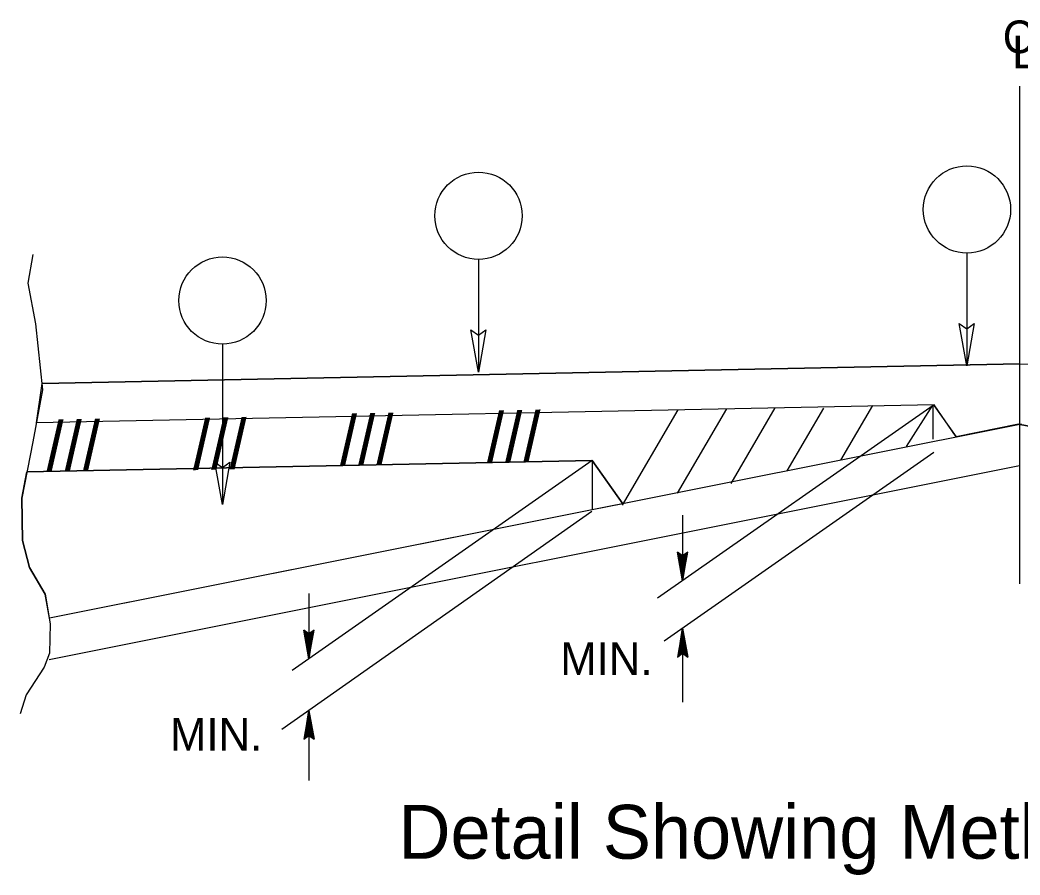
# Model space of a CAD drawing. Extents: x 1818040 to 1825768, y 638918 to 648046.
# Drawn here: x 1822960 to 1824344, y 641816 to 643000 of the extents above; entities that cross this region are included whole.
import ezdxf

# ---------------------------------------------------------------- set-up
doc = ezdxf.new("R2010")
doc.units = 0
for name, color, linetype in [('Typical Detail Wedge2 CELL', 7, 'Continuous'), ('Typical ID Circle CELL', 7, 'Continuous'), ('Typical Terminator CELL', 7, 'Continuous'), ('Typical Text Centerline CELL', 7, 'Continuous'), ('Typical Text General CELL', 7, 'Continuous')]:
    doc.layers.add(name, color=color, linetype=linetype)

msp = doc.modelspace()

# ---------------------------------------------------------------- linework, layer by layer
at = {"layer": 'Typical Detail Wedge2 CELL'}
for p, q in [((1824343.8, 642219), (1824343.8, 642908.2)), ((1824343.8, 642219), (1824343.8, 642689.7)), ((1824343.8, 642523.5), (1822991, 642496.5)), ((1822991, 642496.5), (1824343.8, 642523.5)), ((1824343.8, 642523.5), (1825696.6, 642496.5)), ((1822983.3, 642442.1), (1822991, 642496.5)), ((1824225.1, 642466.9), (1822983.3, 642442.1)), ((1824225.1, 642466.9), (1822983.3, 642442.1)), ((1823870.3, 642459.8), (1823793.4, 642328.1)), ((1824223.6, 642465.9), (1823842.4, 642199)), ((1823937.8, 642461.2), (1823869.8, 642344.4)), ((1824004.6, 642462.5), (1823943.6, 642357.8)), ((1824072, 642462.4), (1824021.3, 642375.7)), ((1824139.9, 642465.8), (1824095.7, 642390.2)), ((1824186.7, 642409.1), (1824223.4, 642466.4)), ((1824223.4, 642466.4), (1824223.4, 642419.3)), ((1824255.5, 642422.4), (1824225.1, 642466.9)), ((1824225.1, 642465.5), (1824255.5, 642422.4)), ((1824345.8, 642440.3), (1823001.2, 642171.3)), ((1824341.8, 642440.3), (1824255.5, 642422.4)), ((1824341.8, 642440.3), (1825686.5, 642171.3)), ((1824432.1, 642422.4), (1824341.8, 642440.3)), ((1823752, 642389.6), (1822970.1, 642374)), ((1822970.1, 642374), (1823752, 642389.6)), ((1823752, 642389.6), (1823336.8, 642098.9)), ((1823794.5, 642329.9), (1823752, 642389.6)), ((1823752, 642389.6), (1823752, 642321.4)), ((1823752, 642389.6), (1823794.4, 642330)), ((1824224.5, 642400.7), (1823851.5, 642139.5)), ((1824343.3, 642382.4), (1823000.7, 642113.9)), ((1823752, 642321.5), (1823615.8, 642294.3)), ((1823794.4, 642330), (1823752, 642321.5)), ((1823751.7, 642319.3), (1823322.5, 642017.3)), ((1823877.1, 642314), (1823877.1, 642223.3)), ((1823615.8, 642294.3), (1823001.2, 642171.3)), ((1823877.1, 642223.3), (1823870.1, 642263.1)), ((1823877.1, 642257.9), (1823870.1, 642263.1)), ((1823877.1, 642223.3), (1823871.1, 642262.3)), ((1823872.1, 642261.6), (1823877.1, 642223.3)), ((1823877.1, 642223.3), (1823873.1, 642260.9)), ((1823874.1, 642260.1), (1823877.1, 642223.3)), ((1823877.1, 642223.3), (1823875.1, 642259.4)), ((1823876.1, 642258.6), (1823877.1, 642223.3)), ((1823877.1, 642223.3), (1823884.2, 642263.1)), ((1823884.2, 642263.1), (1823877.1, 642257.9)), ((1823883.2, 642262.3), (1823877.1, 642223.3)), ((1823877.1, 642223.3), (1823882.1, 642261.6)), ((1823881.1, 642260.9), (1823877.1, 642223.3)), ((1823877.1, 642223.3), (1823880.1, 642260.1)), ((1823879.1, 642259.4), (1823877.1, 642223.3)), ((1823877.1, 642223.3), (1823878.1, 642258.6)), ((1823877.1, 642257.9), (1823877.1, 642223.3)), ((1823360.2, 642205.6), (1823360.2, 642115.2)), ((1823360.2, 642115.2), (1823353.2, 642155)), ((1823360.2, 642149.9), (1823353.2, 642155)), ((1823360.2, 642115.2), (1823354.1, 642154.3)), ((1823360.2, 642115.2), (1823367.2, 642155)), ((1823367.2, 642155), (1823360.2, 642149.9)), ((1823366.2, 642154.3), (1823360.2, 642115.2)), ((1823877.1, 642157.5), (1823870.1, 642117.7)), ((1823871.1, 642118.5), (1823877.1, 642157.5)), ((1823877.1, 642157.5), (1823872.1, 642119.2)), ((1823873.1, 642120), (1823877.1, 642157.5)), ((1823877.1, 642157.5), (1823874.1, 642120.7)), ((1823875.1, 642121.4), (1823877.1, 642157.5)), ((1823877.1, 642157.5), (1823876.1, 642122.1)), ((1823877.1, 642157.5), (1823877.1, 642055.4)), ((1823877.1, 642157.5), (1823884.2, 642117.7)), ((1823877.1, 642122.9), (1823877.1, 642157.5)), ((1823878.1, 642122.1), (1823877.1, 642157.5)), ((1823877.1, 642157.5), (1823879.1, 642121.4)), ((1823880.1, 642120.7), (1823877.1, 642157.5)), ((1823877.1, 642157.5), (1823881.1, 642120)), ((1823882.1, 642119.2), (1823877.1, 642157.5)), ((1823877.1, 642157.5), (1823883.2, 642118.5)), ((1823355.2, 642153.5), (1823360.2, 642115.2)), ((1823360.2, 642115.2), (1823356.2, 642152.8)), ((1823357.2, 642152.1), (1823360.2, 642115.2)), ((1823360.2, 642115.2), (1823358.2, 642151.4)), ((1823359.2, 642150.6), (1823360.2, 642115.2)), ((1823360.2, 642115.2), (1823365.2, 642153.5)), ((1823364.2, 642152.8), (1823360.2, 642115.2)), ((1823360.2, 642115.2), (1823363.2, 642152.1)), ((1823362.3, 642151.4), (1823360.2, 642115.2)), ((1823360.2, 642115.2), (1823361.2, 642150.6)), ((1823360.2, 642149.9), (1823360.2, 642115.2)), ((1823870.1, 642117.7), (1823877.1, 642122.9)), ((1823877.1, 642122.9), (1823884.2, 642117.7)), ((1823360.2, 642043.7), (1823353.2, 642003.9)), ((1823354.2, 642004.7), (1823360.2, 642043.7)), ((1823360.2, 642043.7), (1823355.2, 642005.4)), ((1823356.2, 642006.2), (1823360.2, 642043.7)), ((1823360.2, 642043.7), (1823357.2, 642006.9)), ((1823358.2, 642007.6), (1823360.2, 642043.7)), ((1823360.2, 642043.7), (1823359.2, 642008.3)), ((1823360.2, 642043.7), (1823360.2, 641947)), ((1823360.2, 642043.7), (1823367.2, 642003.9)), ((1823360.2, 642009.1), (1823360.2, 642043.7)), ((1823361.2, 642008.3), (1823360.2, 642043.7)), ((1823360.2, 642043.7), (1823362.3, 642007.6)), ((1823363.3, 642006.9), (1823360.2, 642043.7)), ((1823360.2, 642043.7), (1823364.2, 642006.2)), ((1823365.2, 642005.4), (1823360.2, 642043.7)), ((1823360.2, 642043.7), (1823366.2, 642004.7)), ((1823353.2, 642003.9), (1823360.2, 642009.1)), ((1823360.2, 642009.1), (1823367.2, 642003.9))]:
    msp.add_line(p, q, dxfattribs=at)
for points in [[(1822978.4, 642675), (1822971.2, 642635.4), (1822982.1, 642579), (1822991.6, 642487.8), (1822978.4, 642415.8), (1822962.9, 642337.8), (1822964.1, 642279), (1822973.7, 642241.8), (1822995.3, 642204.6), (1823002.4, 642163.8), (1823001.3, 642123), (1822994, 642103.8), (1822968.9, 642065.4), (1822960.5, 642039)], [(1823001.1, 642171.3), (1822995.3, 642204.6), (1822973.7, 642241.8), (1822964.1, 642279), (1822962.9, 642337.8), (1822970.1, 642374)]]:
    msp.add_lwpolyline(points, dxfattribs=at)
at = {"layer": 'Typical ID Circle CELL'}
for p, q in [((1823594.8, 642668.1), (1823594.8, 642512)), ((1824270.4, 642676.8), (1824270.4, 642520.7)), ((1823240.6, 642550.8), (1823240.6, 642328.8))]:
    msp.add_line(p, q, dxfattribs=at)
for centre in [(1824270.4, 642737.3), (1823594.8, 642728.6), (1823240.6, 642611.2)]:
    msp.add_circle(centre, 60.4, dxfattribs=at)
at = {"layer": 'Typical Terminator CELL'}
for points in [[(1823604.8, 642570.6), (1823594.8, 642512), (1823584.3, 642570.9), (1823594.8, 642563.4)], [(1823604.8, 642570.6), (1823594.8, 642512), (1823584.3, 642570.9), (1823594.8, 642563.4)], [(1824280.4, 642579.3), (1824270.4, 642520.7), (1824259.9, 642579.6), (1824270.4, 642572.1)], [(1824280.4, 642579.3), (1824270.4, 642520.7), (1824259.9, 642579.6), (1824270.4, 642572.1)], [(1823250.7, 642387.4), (1823240.6, 642328.8), (1823230.2, 642387.7), (1823240.6, 642380.2)], [(1823250.7, 642387.4), (1823240.6, 642328.8), (1823230.2, 642387.7), (1823240.6, 642380.2)]]:
    msp.add_lwpolyline(points, close=True, dxfattribs=at)

# ---------------------------------------------------------------- texts
at = {"layer": 'Typical Detail Wedge2 CELL'}
for height, rotation, p in [(67.82, 1.1463, (1823606.4, 642387.5)), (67.84, 1.1447, (1822997, 642374.9)), (67.84, 1.1464, (1823199.8, 642377.3)), (67.81, 1.1445, (1823403, 642383.3))]:
    msp.add_text('/// ', height=height, rotation=rotation, dxfattribs=at).set_placement(p)
for p in [(1823707.9, 642092.9), (1823168, 641988.1)]:
    msp.add_text('MIN.', height=45.19, dxfattribs=at).set_placement(p)
at = {"layer": 'Typical Text Centerline CELL'}
for s, height, p in [('C SURVEY ', 45.19, (1824319.9, 642953.7)), ('L', 45.2, (1824333.1, 642932.6))]:
    msp.add_text(s, height=height, dxfattribs=at).set_placement(p)
at = {"layer": 'Typical Text General CELL'}
msp.add_text('Detail Showing Method of Wedging', height=74.597, dxfattribs=at).set_placement((1823484, 641838.5))

doc.saveas('drawing.dxf')
